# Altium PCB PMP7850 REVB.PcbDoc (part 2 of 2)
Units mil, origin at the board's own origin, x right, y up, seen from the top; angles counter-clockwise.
Board outline 4000 x 3000 mil, 4 copper layers (Top Layer, MidLayer1, MidLayer2, Bottom Layer), stack 61.2 mil thick; 106 components, 51 nets, 290 pads, 278 vias.
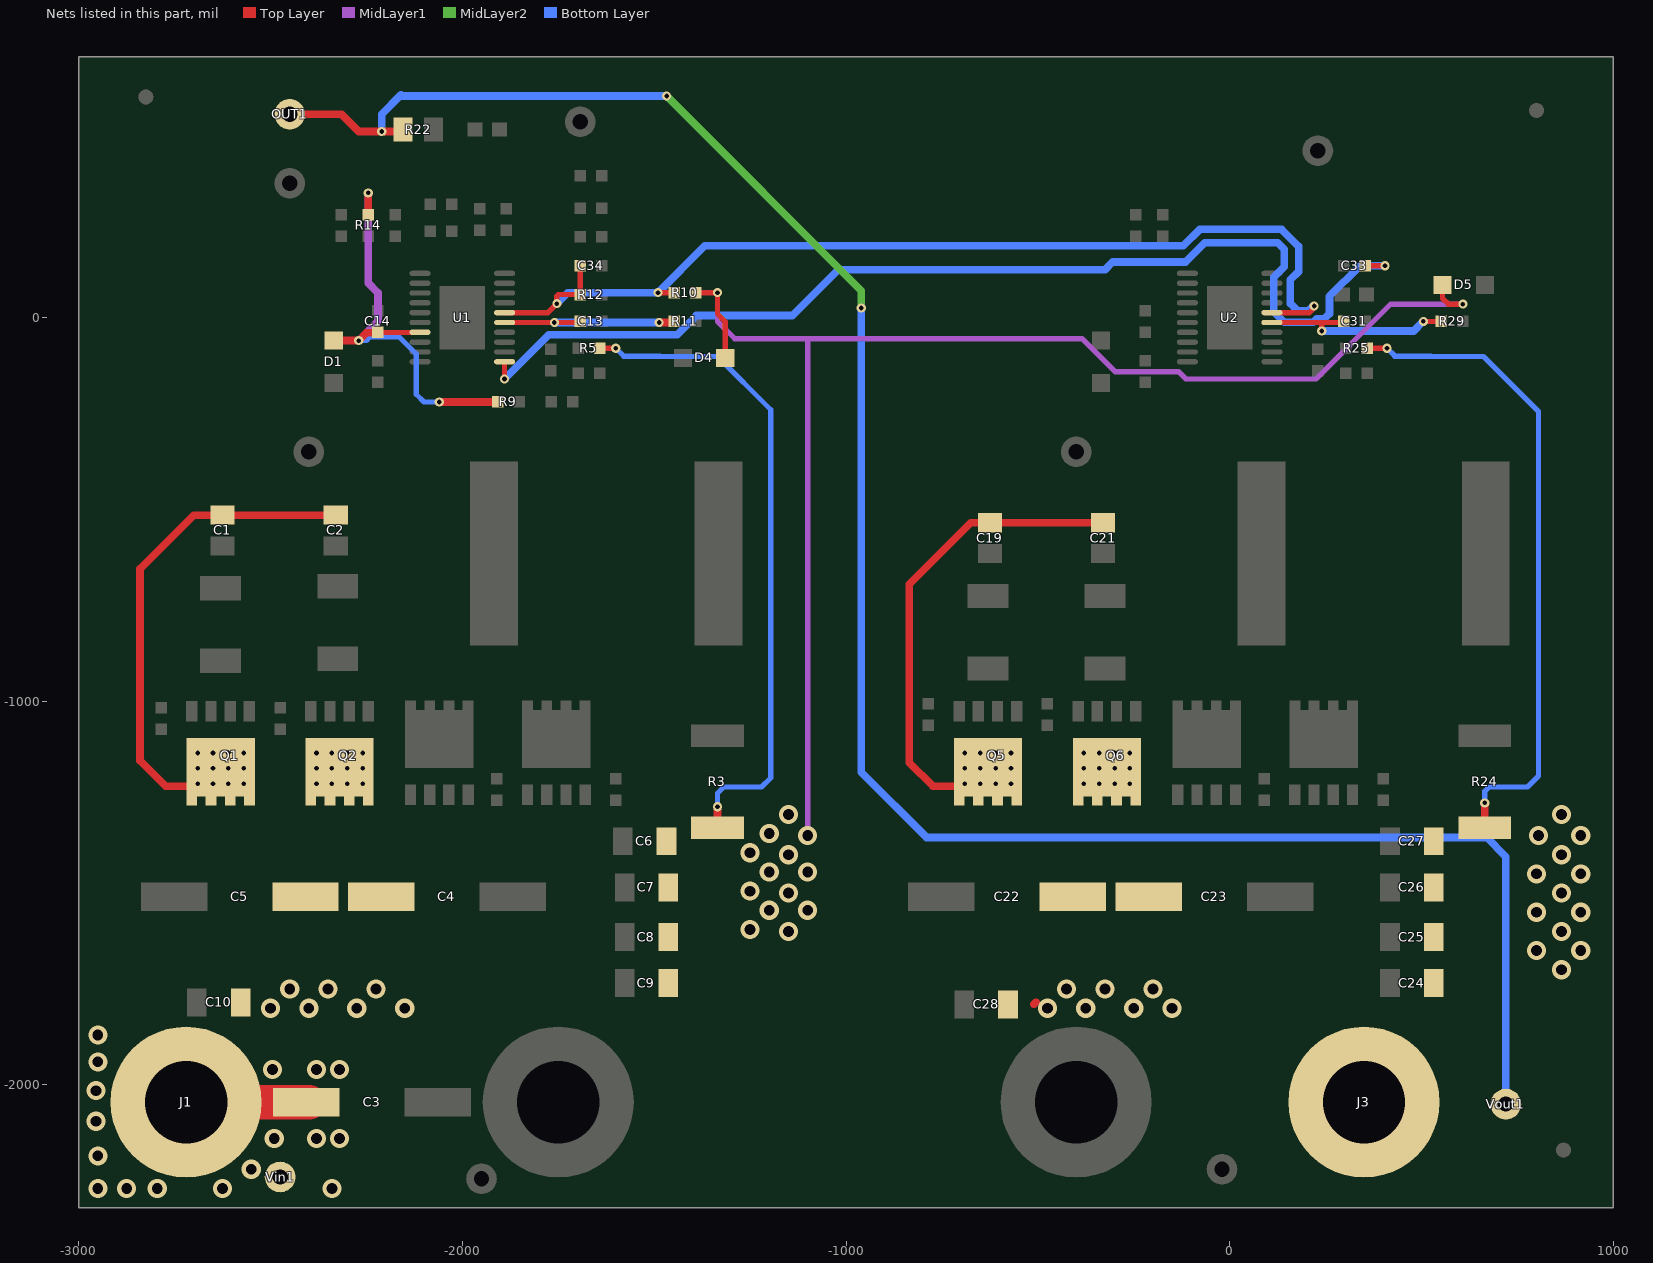
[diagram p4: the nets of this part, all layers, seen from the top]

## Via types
v1: diameter 24, hole 12, Top Layer to Bottom Layer, 169 vias
v2: diameter 50, hole 28, Top Layer to Bottom Layer, 101 vias
v3: diameter 30, hole 15, Top Layer to Bottom Layer, 8 vias

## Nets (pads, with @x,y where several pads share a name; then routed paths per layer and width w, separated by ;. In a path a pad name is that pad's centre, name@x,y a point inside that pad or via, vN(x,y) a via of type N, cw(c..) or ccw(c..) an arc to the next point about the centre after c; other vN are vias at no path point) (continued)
"SYNC OUT1": C33.1 U1.1 | length 2845.8
  Top Layer w13.78: v1(-1890,-160) -1890,-115.39 U1.1@-1889.76,-115.16 ; C33.1@353,135 v1(405,135)
  Bottom Layer w20: v1(-1890,-160) -1774.8,-44.8 -1440,-44.8 -1390,5.2 -1139.8,5.2 -1020,125 -325,125 -305,145 -115,145 -65,195 125,195 142.24,177.76 142.24,132.24 115,105 115,15 142,-12 217.75,-12 226.75,-3 247,-3 260,10 260,55 340,135 v1(405,135)
UVLO: C34.1 R10.1 R12.2 U1.6 U2.6 | length 2720.9
  Top Layer w13.78: U1.6@-1889.76,12.8 -1777.2,12.8 v1(-1753.6,36.4) -1753.6,56.4 -1750,60 R12.2@-1701.5,60 ; R12.2@-1693,60 C34.1@-1693,135 ; v1(-1490,65) R10.1@-1448,65 ; U2.6@110.24,12.8 207.8,12.8 220,25 v1(220,30)
  Bottom Layer w20: v1(-1753.6,36.4) -1725,65 v1(-1490,65) -1368.24,186.76 -120.55,186.76 -77.32,230 135,230 180,185 180,120 158,98 158,36.75 176.75,18 205.32,18 217.32,30 v1(220,30)
VCC: C14.1 D1.2 R9.2 R14.2 U1.17 | length 1205
  Top Layer w13.78: C14.1@-2219.61,-38.39 -2219.11,-38.89 -2110.74,-38.89 U1.17@-2110.24,-38.39
  Top Layer w20: D1.2@-2335,-59.88 -2270.12,-59.88 -2250,-39.76 -2221.76,-39.76 C14.1@-2220,-38 ; R14.2@-2245,268 v1(-2245,325) ; v1(-2060,-220) R9.2@-1908,-220
  MidLayer1 w20: v1(-2270,-60) -2220,-10 -2220,65 -2245,90 v1(-2245,325)
  Bottom Layer w13.78: v1(-2270,-60) -2250,-60 -2240,-50 -2165,-50 -2120,-95 -2120,-200 -2100,-220 v1(-2060,-220)
VIN1: C13.1 R11.1 U1.5 | length 501.1
  Top Layer w13.78: U1.5@-1889.76,-12.8 v1(-1760,-12.8) -1705.8,-12.8 C13.1@-1703,-10
  Top Layer w20: v1(-1487.2,-12.8) -1450.8,-12.8 R11.1@-1448,-10
  Bottom Layer w20: v1(-1760,-12.8) v1(-1487.2,-12.8)
VIN2: C31.1 R29.1 U2.5 | length 532.5
  Top Layer w13.78: U2.5@110.24,-12.8 240,-12.8 ; v1(240,-35) 240,-12.8 ; C31.1@297,-10 294.2,-12.8 240,-12.8 ; v1(505,-10) R29.1@552,-10
  Bottom Layer w20: v1(240,-35) 480,-35 v1(505,-10)
"VIN 6-8.4V": C3.1 C6.1 C7.1 C8.1 C9.1 C24.1 C25.1 C26.1 C27.1 D4.2 D5.2 J1.1 R3.1 R5.2 R10.2 R24.1 R25.2 Vin1.1 | length 7543.2
  Top Layer w13.78: R5.2@-1642,-80 v1(-1600,-80) ; R10.2@-1392,65 v1(-1335,65) -1335,10 -1314.88,-10.12 D4.2@-1314.88,-105 ; R25.2@358,-80 v1(410,-80) ; D5.2@554.88,85 554.88,50.12 570,35 v1(608,35)
  Top Layer w20: R3.1@-1335,-1330.08 v1(-1335,-1275) ; R24.1@665,-1330.08 v1(665,-1265)
  Top Layer w90: J1.1@-2720,-2045 C3.1@-2398.7,-2045
  MidLayer1 w13.78: v1(-1335,65) -1335,-10 -1290,-55 -1105,-55 ; v2(-1100,-1350) -1100,-60 -1105,-55 ; v1(608,35) 420,35 225,-160 -114.14,-160 -133.25,-140.89 -299.11,-140.89 -385,-55 -1105,-55
  Bottom Layer w13.78: v1(-1600,-80) -1579.39,-100.61 -1485.15,-100.61 -1484.54,-101.22 -1335.15,-101.22 -1196.22,-240.15 -1196.22,-1199.85 -1220.15,-1223.78 -1318.78,-1223.78 -1335,-1240 v1(-1335,-1275) ; v1(410,-80) 430.61,-100.61 524.85,-100.61 525.46,-101.22 661.22,-101.22 805,-245 805,-1195 776.22,-1223.78 676.22,-1223.78 665,-1235 v1(665,-1265)
  other v2: -2950,-2270 -2875,-2270 -2795,-2270 -2625,-2270 -2340,-2270 -2550,-2220 -2950,-2185 -2490,-2140 -2380,-2140 -2320,-2140 -2955,-2095 -2955,-2015 -2495,-1960 -2380,-1960 -2320,-1960 -2950,-1940 -2950,-1870 865,-1700 800,-1650 915,-1650 -1150,-1600 865,-1600 -1250,-1595 800,-1550 915,-1550 -1200,-1545 -1100,-1545 -1150,-1500 865,-1500 -1250,-1495 800,-1450 915,-1450 -1200,-1445 -1100,-1445 -1150,-1400 865,-1400 -1250,-1395 805,-1350 915,-1350 -1200,-1345 -1150,-1295 865,-1295
"VOUT +12V": C1.1 C2.1 C4.1 C5.1 C10.1 C19.1 C21.1 C22.1 C23.1 C28.1 J3.1 OUT1.1 Q1.5 Q1.6 Q1.7 Q1.8 Q1.9 Q2.5 Q2.6 Q2.7 Q2.8 Q2.9 Q5.5 Q5.6 Q5.7 Q5.8 Q5.9 Q6.5 Q6.6 Q6.7 Q6.8 Q6.9 R22.1 Vout1.1 | length 8145.6
  Top Layer w20: Q1.9@-2600,-1221.98 -2773.02,-1221.98 -2840,-1155 -2840,-655 -2700,-515 C2.1@-2330,-515 ; OUT1.1@-2450,530 -2315,530 -2270,485 v1(-2210,485) R22.1@-2160,485 ; Q5.9@-600,-1221.98 -773.02,-1221.98 -835,-1160 -835,-695 -675,-535 C21.1@-330,-535 ; -510,-1790 -505,-1785
  MidLayer2 w20: v1(-1467.5,577.5) -960.12,70.12 v1(-960.12,25)
  Bottom Layer w20: v1(-2210,485) -2210,530 -2160,580 ; -2160,577.5 v1(-1467.5,577.5) ; v1(-960.12,25) -960.12,-1185.12 -790.24,-1355 670,-1355 720,-1405 Vout1.1@720,-2050
  other v1: -2690,-1215 -2650,-1215 -2610,-1215 -2570,-1215 -2380,-1215 -2340,-1215 -2300,-1215 -2260,-1215 -690,-1215 -650,-1215 -610,-1215 -570,-1215 -380,-1215 -340,-1215 -300,-1215 -260,-1215 -2690,-1175 -2650,-1175 -2610,-1175 -2570,-1175 -2380,-1175 -2340,-1175 -2300,-1175 -2260,-1175 -690,-1175 -650,-1175 -610,-1175 -570,-1175 -380,-1175 -340,-1175 -300,-1175 -260,-1175 -2690,-1135 -2650,-1135 -2610,-1135 -2570,-1135 -2380,-1135 -2340,-1135 -2300,-1135 -2260,-1135 -690,-1135 -650,-1135 -610,-1135 -570,-1135 -380,-1135 -340,-1135 -300,-1135 -260,-1135
  other v2: -2500,-1800 -2400,-1800 -2275,-1800 -2150,-1800 -475,-1800 -375,-1800 -250,-1800 -150,-1800 -2450,-1750 -2350,-1750 -2225,-1750 -425,-1750 -325,-1750 -200,-1750
pads on no net: FID1.1 FID2.1 FID3.1 FID4.1 FID5.1 FID6.1 Q1.0 Q2.0 Q3.0 Q4.0 Q5.0 Q6.0 Q7.0 Q8.0 U2.1

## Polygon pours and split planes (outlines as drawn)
GND on Top Layer "Top Layer-GND" (solid, remove dead copper, pour order 42): -1230,705 -1230,465 -2430,465 -2430,-355 -2560,-485 -2635,-485 -2810,-660 -2810,-1255 -3000,-1255 -3005,-1260 -3005,685
GND on Top Layer "Top Layer-GND" (solid, remove dead copper, pour order 44): -2365,250 -2365,360 -2285,440 -1480,440 -1480,-250 -1730,-250 -1730,-200 -1560,-200 -1560,-35 -1665,-35 -1665,330 -1715,330 -1715,245 -1745,215 -1745,185 -1845,85 -1855,85 -1855,265 -1910,265 -1910,330 -2145,330 -2145,250 -2200,250 -2200,355 -2285,355 -2295,345 -2295,250
GND on Top Layer "Top Layer-GND" (solid, remove dead copper, pour order 35): -2160,-1220.1 -2160,-1330.2 -2100,-1390.2 -2100,-2320.2 -1535,-2320.2 -1535,-1300 -1715,-1300 -1715,-1220.08 -1845,-1219.87 -1845,-1300 -2020,-1300 -2020,-1219.96
CSN1_N on Top Layer "Top Layer-CSN1_N" (solid, remove dead copper, pour order 30): -1415,-375 -1415,-1120 -1245,-1120 -1245,-375
SW1_P on Top Layer "Top Layer-SW1" (solid, remove dead copper, pour order 26): -1665,-355 -1665,-1175 -2210,-1175 -2210,-1055 -2670,-1055 -2670,-985 -2700,-985 -2700,-770 -2255,-770 -2255,-355
"VIN 6-8.4V" on Top Layer "Top Layer-VIN 6-8.4V" (solid, remove dead copper, pour order 40): 485,-1250 995,-1250 995,-1790 485,-1790
"VIN 6-8.4V" on Top Layer "Top Layer-VIN 6-8.4V" (solid, remove dead copper, pour order 48): -3005,-1835 -3005,-2320 -3000,-2315 -2275,-2315 -2275,-1835
GND on Top Layer "Top Layer-GND" (solid, remove dead copper, pour order 41): 1000,-1801.75 1000,-2319.37 1005,-2325 -2250,-2325 -2250,-1801.75
GND on Top Layer "Top Layer-No Net" (solid, remove dead copper, pour order 46): -195,250 -195,340 470,340 470,-25 475,-30 335,-30 335,80 430,80 430,165 290,165 215,90 180,90 140,85 140,220 115,250
"VIN 6-8.4V" on Top Layer "Top Layer-VIN 6-8.4V" (solid, remove dead copper, pour order 34): -1015,-1790 -1015,-1250 -1510,-1250 -1510,-1790
GND on Top Layer "Top Layer-GND" (solid, remove dead copper, pour order 39): -1430,685 -380,685 -380,-495 -670,-495 -810,-635 -810,-1225 -1645,-1225 -1645,-300 -1430,-300
GND on Top Layer "Top Layer-GND" (solid, remove dead copper, pour order 43): -660,685 -660,370 525,370 525,-195 -165,-195 -165,-405 350,-405 350,-1225 1005,-1225 1005,685
CSN2_N on Top Layer "Top Layer-CSN2_N" (solid, remove dead copper, pour order 32): 580,-375 755,-375 755,-1115 750,-1120 580,-1120
GND on Top Layer "Top Layer-GND" (solid, remove dead copper, pour order 36): -1005,-1250 -745,-1250 -745,-1460 -570,-1460 -570,-1755 -571.45,-1756.45 -566.42,-2325 -1005,-2325
SW2_P on Top Layer "Top Layer-SW2" (solid, remove dead copper, pour order 27): 335,-400 -255,-400 -255,-795 -700,-795 -700,-985 -675,-985 -675,-1030 -675,-1050 -525,-1050 -525,-1030 -360,-1030 -360,-1050 -160,-1050 -160,-1175 335,-1175
GND on Top Layer "Top Layer-GND" (solid, remove dead copper, pour order 37): -165,-1215 -165,-1330.31 -105,-1390.59 -105,-2320 475,-2320 475,-1290 285,-1290 285,-1215 155,-1215 155,-1295 -20,-1295 -20,-1215
"VOUT +12V" on Top Layer "Top Layer-VOUT +12V" (solid, remove dead copper, pour order 29): -720,-1095 -220,-1095 -220,-1335 -180,-1335 -115,-1400 -115,-1830 -560,-1830 -560,-1450 -720,-1450
GND on Top Layer "Top Layer-GND" (solid, remove dead copper, pour order 38): -3005,-1300 -2745,-1300 -2745,-1380 -2615,-1510 -2615,-1815 -3005,-1815
"VOUT +12V" on Top Layer "Top Layer-VOUT" (solid, remove dead copper, pour order 28): -2720,-1095 -2220,-1095 -2220,-1335 -2190,-1335 -2115,-1410 -2115,-1895 -2605,-1895 -2605,-1485 -2620,-1485 -2720,-1385
"VIN 6-8.4V" on MidLayer1 "MidLayer1-VIN 6-8.4V" (solid, remove dead copper, pour order 31): -3005,-2325 1005,-2325 1005,-470 -3005,-470
GND on MidLayer1 "MidLayer1-GND" (solid, remove dead copper, pour order 45): -3000,685 1005,685 1005,-420 -3000,-420
"VOUT +12V" on Bottom Layer "Bottom Layer-VOUT +12V" (solid, remove dead copper, pour order 33): -3010,-2320 1005,-2320 1010,-2325 1010,-1375 -3004.81,-1375
GND on Bottom Layer "Bottom Layer-GND" (solid, remove dead copper, pour order 25): -3005,685 1000,685 1000,-1400 -3005,-1400
GND on MidLayer2 "MidLayer2-GND" (solid, remove dead copper, pour order 47): -3000,-2345 1000,-2345 1000,680 -3000,680

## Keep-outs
Keep-Out Layer:
  lines w10: -3005,685 -3005,-2325 1005,-2325 1005,685 -3000,685
  text ".Layer_Name" at -2423,-3178.49 h60
  text "880" at 117.5,-3178.49 h60

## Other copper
Top Layer:
  rectangle net GND: -2060,-150 -1940,170
  rectangle net GND: -60,-155 60,155
  pour cut-out: -1365,-1300 -1365,-1255 -1300,-1255 -1300,-1300
  pour cut-out: 635,-1245 700,-1245 700,-1290 635,-1290
  text ".Layer_Name" at -2423,-3178.49 h60
  text "880" at 117.5,-3178.49 h60
MidLayer1:
  pour cut-out: 635,-1240 635,-1290 700,-1290 700,-1240
  pour cut-out: -1365,-1250 -1300,-1250 -1300,-1300 -1365,-1300
Bottom Layer:
  pour cut-out: 735,-2015 735,-1435 705,-1435 705,-2015
  pour cut-out: 620,-1120 755,-1120 755,-285 625,-155 450,-155 450,-185 375,-185 375,-45 660,-45 830,-215 830,-1265 790,-1305 620,-1305
  pour cut-out: -1635,-50 -1635,-170 -1545,-170 -1545,-150 -1360,-150 -1245,-265 -1245,-1110 -1370,-1110 -1370,-1310 -1305,-1310 -1270,-1275 -1180,-1275 -1170,-1265 -1170,-225 -1320,-75 -1545,-75 -1545,-50
  text ".Layer_Name" at -2423,-3178.49 h60
  text "880" at 117.5,-3178.49 h60

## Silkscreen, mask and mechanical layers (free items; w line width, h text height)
Top Overlay:
  text ".Pcb_File_Name_No_Path" at -1400,455 h60
  text "©" at -1075,330 h105
  text ".CopyrightYear" at -975,330 h60
  text "TI" at -699,330 h60
  text "SW" at -565,-305 h40
  text "SW" at -2570,-310 h40
  text "VIN" at -2570,-1905 h40
  text "GND" at -1485,-1945 h60
  text "VOUT" at 595,-1950 h60
  text "GND" at -150,-1955 h60
  text ".Layer_Name" at -2423,-3178.49 h60
  text "880" at 117.5,-3178.49 h60
Bottom Overlay:
  text "MADE IN U.S." at -425,520 h60
  text "UL94V-0" at 90,515 h60
  text ".PCB_SilkRev" at -864,355 h60
  text ".PCB_CopperRev" at -684,355 h60
  text "-" at -625,355 h60
  text ".PRJ_BasePN" at -264,355 h60
  text "551" at -99,355 h60
  text ".Layer_Name" at -2423,-3178.49 h60
  text "880" at 117.5,-3178.49 h60
Top Paste:
  text ".Layer_Name" at -2423,-3178.49 h60
  text "881" at 117.5,-3178.49 h60
Bottom Paste:
  text ".Layer_Name" at -2423,-3178.49 h60
  text "881" at 117.5,-3178.49 h60
Top Solder:
  text ".Layer_Name" at -2423,-3178.49 h60
  text ".Layer_Name" at -2423,-3178.49 h60
  text "880" at 117.5,-3178.49 h60
Bottom Solder:
  text ".Layer_Name" at -2423,-3178.49 h60
  text "880" at 117.5,-3178.49 h60
Drill Guide:
  text ".Layer_Name" at -2423,-3178.49 h60
  text "880" at 117.5,-3178.49 h60
M1 Board Outline:
  the board outline again, w10
  text ".Layer_Name" at -2423,-3178.49 h60
  text "880" at 117.5,-3178.49 h60
M2 Board Dimensions:
  rectangle: -2875.5,-2730.5 -2500.5,-2605.5
  rectangle: -3000.5,-2605.5 -2875.5,-2480.5
  lines w7: -3000.5,-2605.5 -2000.5,-2605.5 ; -2875.5,-2730.5 -2875.5,-2480.5 ; -2750.5,-2730.5 -2750.5,-2480.5 ; -2500.5,-2730.5 -2500.5,-2480.5 ; -2250.5,-2730.5 -2250.5,-2480.5 ; -3000.5,-2730.5 -3000.5,-2480.5 -2000.5,-2480.5 -2000.5,-2730.5 -3000.5,-2730.5
  lines w10: -3000.5,-2795.5 -3000.5,-2775.5 ; -2940.5,-2805.5 -3000.5,-2785.5 ; -2940.5,-2765.5 -3000.5,-2785.5 ; -2776.42,-2785.5 -3000.5,-2785.5 ; -2224.58,-2785.5 -2000.5,-2785.5 ; -2060.5,-2805.5 -2000.5,-2785.5 ; -2060.5,-2765.5 -2000.5,-2785.5 ; -2000.5,-2795.5 -2000.5,-2775.5
  text "1000 (mil)" at -2766.42,-2821.49 h60
  text ".Layer_Name" at -2423,-3178.49 h60
  text "880" at 117.5,-3178.49 h60
M3 3D STEP Top:
  text ".Layer_Name" at -2423,-3178.49 h60
  text "880" at 117.5,-3178.49 h60
M4 3D STEP Bottom:
  text ".Layer_Name" at -2423,-3178.49 h60
  text "880" at 117.5,-3178.49 h60
M5 Assembly Top:
  lines w7: -3292,-3250.17 3308,-3250.17 ; -3292,-3046.83 3310,-3046.83 ; -3292,-2843.5 -3292,-3453.5 713,-3453.5 3310,-3453.5 3310,-2843.5 -3291.5,-2843.5 -3291.5,-3453.5 -1716,-3453.5 ; -827,-3249 -827,-2843.5 ; 926,-3453 926,-3253 ; 1902,-3250 1902,-3047.17
  text "COMPONENTS MARKED 'DNP' SHOULD NOT BE POPULATED, AND MAY NOT BE IN BILL OF MATERIALS" at -1846.5,-2638.5 h60
  text "ASSEMBLY VARIANT:" at -1847,-2754 h60
  text ".VariantName" at -811,-2754 h60
  text "PCB VIEWED FROM TOP SIDE" at -3228.5,-2975.67 h60
  text "PROJECT NAME =" at -752,-2975.67 h60
  text ".PRJ_Title" at 117.5,-2975.67 h60
  text "-" at 662,-3176.49 h60
  text ".PCB_SilkRev" at 919,-3176.49 h60
  text "TEXAS INSTRUMENTS" at 1973,-3176.49 h60
  text "LAYER NAME =" at -3228.5,-3178.49 h60
  text "ARTWORK #    =" at -752,-3178.49 h60
  text ".prj_BasePN" at 293.5,-3178.49 h60
  text ".PCB_CopperRev" at 729.5,-3178.49 h60
  text "PLOT NAME =" at -3228.5,-3384.34 h60
  text ".plot_File_Name" at -2423,-3384.34 h60
  text "GENERATED    :" at 998,-3384.34 h60
  text ".Print_Date" at 1867.5,-3384.34 h60
  text ".Print_Time" at 2596.5,-3384.34 h60
M6 Assembly Bottom:
  lines w7: -3292,-3046.83 3310,-3046.83 ; -3290,-3250.17 3310,-3250.17 ; -1884,-3250.5 -1884,-3047.17 ; -866,-3453 -866,-3251 ; 845,-3249 845,-2843.5 ; 1734,-3453.5 3309.5,-3453.5 3309.5,-2843.5 -3292,-2843.5 -3292,-3453.5 -695,-3453.5 3310,-3453.5 3310,-2843.5
  text "COMPONENTS MARKED 'DNP' SHOULD NOT BE POPULATED, AND MAY NOT BE IN BILL OF MATERIALS" at 3102,-2638 h60
  text ".VariantName" at 2058,-2754 h60
  text "ASSEMBLY VARIANT:" at 3097,-2754 h60
  text ".PRJ_Title" at -99.5,-2975.67 h60
  text "PROJECT NAME =" at 770,-2975.67 h60
  text "PCB VIEWED FROM BOTTOM SIDE" at 3246.5,-2975.67 h60
  text "-" at -685,-3176.49 h60
  text "TEXAS INSTRUMENTS" at -1955,-3178.49 h60
  text ".PCB_SilkRev" at -916,-3178.49 h60
  text ".PCB_CopperRev" at -715,-3178.49 h60
  text ".prj_BasePN" at -275.5,-3178.49 h60
  text "880" at -92,-3178.49 h60
  text "ARTWORK #    =" at 770,-3178.49 h60
  text "LAYER NAME =" at 3246.5,-3178.49 h60
  text ".Print_Time" at -2578.5,-3384.34 h60
  text ".Print_Date" at -1849.5,-3384.34 h60
  text "GENERATED    :" at -980,-3384.34 h60
  text ".plot_File_Name" at 2441,-3384.34 h60
  text "PLOT NAME =" at 3246.5,-3384.34 h60
M9 Title Sheet:
  drawing of 57 lines, arcs and shapes, not listed
  text "1" at -2260.16,5716.5 h70
  text "2" at 235.5,5716.5 h70
  text "3" at 2724.84,5716.5 h70
  text "4" at 5231.51,5716.5 h70
  text "5" at 7730.5,5716.5 h70
  text "6" at 10235.5,5716.5 h70
  text "A" at -3416.5,4573.5 h70
  text "A" at 11383.5,4573.5 h70
  text "B" at -3416.5,2193.5 h70
  text "B" at 11383.5,2193.5 h70
  text "C" at -3416.5,-181.5 h70
  text "C" at 11383.5,-181.5 h70
  text "PROJECT TITLE:" at 8343.5,-2042.5 h45
  text ".PRJ_Title" at 8393.5,-2175.83 h70
  text "FILE NAME:" at 8343.5,-2343.5 h45
  text ".PCB_File_Name_No_Path" at 8393.5,-2463.5 h70
  text "D" at -3416.5,-2551.5 h70
  text "D" at 11383.5,-2551.5 h70
  text "FAB DRAWING NUMBER:" at 8343.5,-2633.5 h45
  text "551" at 8393.5,-2788.49 h70
  text ".PRJ_BasePN" at 8588.5,-2788.49 h70
  text "-" at 8997,-2788.49 h70
  text ".PCB_CopperRev" at 9070,-2788.49 h70
  text ".PCB_SilkRev" at 9295,-2788.49 h70
  text "Texas Instruments (TI) and/or its licensors do not warrant the accuracy or completeness of this specification" at 3374,-2925.34 h45
  text "DESIGNED FOR:" at 8343.5,-2943.5 h45
  text "or any information contained therein. TI and/or its licensors do not warrant that this design will meet" at 3329.01,-3038 h45
  text ".PRJ_Customer" at 8393.5,-3083.5 h70
  text "the specifications, will be suitable for your application or fit for any particular purpose, or will operate in" at 3329.01,-3150.67 h45
  text ".Layer_Name" at -2423,-3178.49 h60
  text "880" at 117.5,-3178.49 h60
  text "ALTIUM DESIGNER VERSION:" at 9888.5,-3243.5 h45
  text "an implementation. TI and/or its licensors do not warrant that the design is production worthy. You should" at 3329.01,-3263.33 h45
  text ".print_Scale" at 8393.5,-3345.5 h70
  text "completely validate and test your design implementation to confirm the system functionality for your application." at 3374,-3376 h45
  text ".Application_BuildNumber" at 9938.5,-3376.83 h70
  text "1" at -2260.16,-3583.5 h70
  text "2" at 235.5,-3583.5 h70
  text "3" at 2724.84,-3583.5 h70
  text "4" at 5231.51,-3583.5 h70
  text "5" at 7730.5,-3583.5 h70
  text "6" at 10235.5,-3583.5 h70
M10 Fab Notes:
  drawing of 203 lines, arcs and shapes, not listed
  text "DESIGN INFORMATION" at 9381.02,4490 h60
  text "(REFER ALSO ARRAY/PANEL PROFILING INFORMATION)" at 9019.46,4328.29 h60
  text "BOARD SIZE" at 8333.46,4324 h60
  text "4000MIL" at 8795.78,4196.18 h60
  text "X" at 9301.46,4196.18 h60
  text "3000MIL" at 9532.78,4196.18 h60
  text "Number of Layers :" at 8736.46,3999 h60
  text "4" at 9831.27,3989 h60
  text "MIN. TRACK WIDTH:" at 8736.46,3860 h60
  text "13" at 9832.7,3860 h60
  text "MIL" at 9987.46,3860 h60
  text "MIN. CLEARANCE:" at 8736.46,3728 h60
  text "8" at 9832.7,3728 h60
  text "MIL" at 9987.46,3728 h60
  text "MIN. VIA PAD SIZE:" at 8736.46,3596 h60
  text "20" at 9802.71,3596 h60
  text "MIL" at 9987.46,3596 h60
  text "0.127mm (5MIL)" at 9431.46,3454.29 h60
  text "MINIMUM ANNULAR RING" at 8407.23,3450 h60
  text "EXTERNAL" at 10139.46,3450 h60
  text "PER" at 8607.23,3332 h60
  text "IPC-D-275 CLASS 2 LEVEL C" at 8827.23,3332 h60
  text "MIL, HOLES" at 10315.46,3219.71 h60
  text "+/-" at 9923,3219 h60
  text "+/-" at 10777,3219 h60
  text "REGISTRATION TOLERANCES:" at 8407.23,3214 h60
  text "METAL" at 9607,3214 h60
  text "5" at 10183.2,3214 h60
  text "3" at 11016.2,3214 h60
  text "MIL" at 11132.46,3214 h60
  text "MATERIAL:" at 8332.46,3004.54 h60
  text "FR-4 High Tg" at 9318.9,2864.21 h60
  text "FR-4" at 8793.46,2855.64 h60
  text "OTHER" at 10241.46,2855.64 h60
  text "X" at 8605,2855 h60
  text "62 MIL (1.6mm) +/-10%" at 9073.56,2692.92 h60
  text "THICKNESS:" at 8407.23,2688.64 h60
  text "X" at 8945.4,2688.64 h60
  text "OTHER" at 10358.46,2688.64 h60
  text "TOLERANCE:" at 8407.23,2530.64 h60
  text "X" at 9246.53,2530.64 h60
  text "ANSI IPC-6012 TYPE 3 CLASS 2" at 9433.48,2530.64 h60
  text "OTHER +/-" at 9433.46,2374.64 h60
  text "BOW & TWIST:" at 8407.23,2217.64 h60
  text "X" at 9246.53,2217.64 h60
  text "ANSI IPC-6012 TYPE 3 CLASS 2" at 9433.48,2217.64 h60
  text "OTHER +/-" at 9433.46,2059.13 h60
  text "COPPER THICKNESS (FINISHED):" at 8332.46,1923.64 h60
  text "1.4MIL (1oz)" at 9212.46,1770.92 h60
  text "2MIL (1.4oz)" at 9979.46,1770.92 h60
  text "2.8MIL (2oz)" at 10706.46,1770.92 h60
  text "OUTER:" at 8689.46,1766.64 h60
  text "X" at 9084,1766 h60
  text "0.7MIL (0.5oz)" at 9562.46,1613.92 h60
  text "2.8MIL (2oz)" at 10406.46,1613.92 h60
  text "INNER SIGNAL:" at 8689.46,1609.64 h60
  text "X" at 9435.42,1609.64 h60
  text "DRILLING:" at 8332.46,1470.64 h60
  text "REFERENCE:" at 8407.23,1353.64 h60
  text "X" at 9055.46,1353.64 h60
  text "AS SHOWN" at 9242.46,1353.64 h60
  text "X" at 9956.46,1353.64 h60
  text "NC_DRILL FILES" at 10093.46,1353.64 h60
  text "PTH MIN COPPER THICKNESS:" at 8407.23,1195.64 h60
  text "X" at 9757.46,1195.64 h60
  text "1MIL" at 9894.46,1195.64 h60
  text "OTHER" at 10391.46,1195.64 h60
  text "BOARD FINISH:" at 8332.46,1036.64 h60
  text "SILKSCREEN:" at 8487.68,918.64 h60
  text "X" at 9436.46,918.64 h60
  text "TOP" at 9562.46,918.64 h60
  text "X" at 9946.46,918.64 h60
  text "BOTTOM" at 10073.46,918.64 h60
  text "SILKSCREEN COLOR:" at 8487.68,751.64 h60
  text "X" at 9435.42,751.64 h60
  text "WHITE" at 9562.46,751.64 h60
  text "OTHER" at 10073.46,751.64 h60
  text "SOLDER RESIST COLOR:" at 8487.68,581.64 h60
  text "X" at 9055.42,422.44 h60
  text "GREEN" at 9182.46,422.44 h60
  text "BLUE" at 9773.46,422.44 h60
  text "OTHER" at 10311.46,422.44 h60
  text "IMMERSION GOLD (ENIG)" at 9393.46,233.92 h60
  text "SURFACE FINISH:" at 8332.46,229.64 h60
  text "Pb-FREE HASL" at 10625.75,229.64 h60
  text "X" at 10485,225 h60
  text "OTHER" at 9393.46,72.64 h60
  text "X" at 9200,-100 h60
  text "ARRAY/PANEL:" at 8332.46,-106.36 h60
  text "CUT AND TRIM PER MECH LAYER 1" at 9393.46,-110.65 h60
  text "N.C. ROUTE" at 9393.46,-262.36 h60
  text "V. SCORE" at 10259.46,-262.36 h60
  text "CERTIFICATION:" at 8332.46,-399.36 h60
  text "MATERIALS AND WORKMANSHIP FOR ALL PCBS" at 9057.46,-399.36 h60
  text "TO MEET OR EXCEED THE REQUIREMENTS OF:" at 9057.46,-497.36 h60
  text "X" at 8683.96,-633.87 h60
  text "ANSI IPC-A-600F CLASS ->" at 8822.96,-633.87 h60
  text "X" at 10462.02,-633.87 h60
  text "2" at 10580.96,-633.86 h60
  text "1" at 10265.96,-635.36 h60
  text "3" at 10934.96,-635.36 h60
  text "X" at 8686.02,-793.36 h60
  text "UL 94V-0" at 8822.96,-793.36 h60
  text "X" at 9498.02,-793.36 h60
  text "RoHS" at 9634.96,-793.36 h60
  text "OTHER" at 10279.36,-793.36 h60
  text "PER ORDER" at 10676.42,-793.36 h60
  text "ADDITIONAL REQUIREMENTS:" at 8332.46,-934.36 h60
  text "MICROSECTION:" at 8407.23,-1049.36 h60
  text "YES" at 9312.96,-1049.36 h60
  text "X" at 10640,-1205 h60
  text "REQUIRED" at 10174.46,-1205.51 h60
  text "BARE BOARD ELEC. TEST:" at 8407.23,-1208.36 h60
  text "NONE" at 9712.96,-1208.36 h60
  text "PER ORDER" at 10766.46,-1208.36 h60
  text "MANUFACTURER'S ID/LOGO:" at 8407.23,-1365.36 h60
  text "RAIL" at 9872.96,-1369.65 h60
  text "METAL" at 10364.77,-1369.65 h60
  text "X" at 10750,-1370 h60
  text "SILK" at 10876.46,-1369.65 h60
  text ".Layer_Name" at -2423,-3178.49 h60
  text "880" at 117.5,-3178.49 h60
M11 Gerber Information:
  lines w7: -3292,-3250.17 3308,-3250.17 ; -3292,-3046.83 3310,-3046.83 ; -3292,-2843.5 -3292,-3453.5 713,-3453.5 3310,-3453.5 3310,-2843.5 -3291.5,-2843.5 -3291.5,-3453.5 -1716,-3453.5 ; -827,-3249 -827,-2843.5 ; 926,-3453 926,-3253 ; 1902,-3250 1902,-3047.17
  text "ALL ARTWORK VIEWED FROM TOP SIDE" at -3228.5,-2975.67 h60
  text "PROJECT NAME =" at -752,-2975.67 h60
  text ".PRJ_Title" at 117.5,-2975.67 h60
  text "-" at 662,-3176.49 h60
  text ".PCB_SilkRev" at 919,-3176.49 h60
  text "TEXAS INSTRUMENTS" at 1973,-3176.49 h60
  text "LAYER NAME =" at -3228.5,-3178.49 h60
  text "ARTWORK #    =" at -752,-3178.49 h60
  text ".prj_BasePN" at 293.5,-3178.49 h60
  text ".PCB_CopperRev" at 729.5,-3178.49 h60
  text "PLOT NAME =" at -3228.5,-3384.34 h60
  text ".plot_File_Name" at -2423,-3384.34 h60
  text "GENERATED    :" at 998,-3384.34 h60
  text ".Print_Date" at 1867.5,-3384.34 h60
  text ".Print_Time" at 2596.5,-3384.34 h60
M12 Stackup:
  drawing of 295 lines, arcs and shapes, not listed
  text "Layer" at 2276.2,4425 h60
  text "Name" at 2686.11,4425 h60
  text "Material" at 3615.85,4425 h60
  text "Thickness" at 4475.62,4425 h60
  text "Constant" at 5125.46,4425 h60
  text "Board Layer Stack" at 5695.32,4425 h60
  text "1" at 2276.2,4305 h60
  text "Top Overlay" at 2686.11,4305 h60
  text "2" at 2276.2,4185 h60
  text "Top Solder" at 2686.11,4185 h60
  text "Solder Resist" at 3615.85,4185 h60
  text "0.40mil" at 4475.62,4185 h60
  text "3.5" at 5125.46,4185 h60
  text "3" at 2276.2,4065 h60
  text "Top Layer" at 2686.11,4065 h60
  text "Copper" at 3615.85,4065 h60
  text "1.40mil" at 4475.62,4065 h60
  text "4" at 2276.2,3945 h60
  text "Dielectric1" at 2686.11,3945 h60
  text "FR-4" at 3615.85,3945 h60
  text "12.60mil" at 4475.62,3945 h60
  text "4.8" at 5125.46,3945 h60
  text "5" at 2276.2,3825 h60
  text "MidLayer1" at 2686.11,3825 h60
  text "Copper" at 3615.85,3825 h60
  text "0.70mil" at 4475.62,3825 h60
  text "6" at 2276.2,3705 h60
  text "Dielectric2" at 2686.11,3705 h60
  text "FR-4" at 3615.85,3705 h60
  text "31.80mil" at 4475.62,3705 h60
  text "4.8" at 5125.46,3705 h60
  text "7" at 2276.2,3585 h60
  text "MidLayer2" at 2686.11,3585 h60
  text "Copper" at 3615.85,3585 h60
  text "0.70mil" at 4475.62,3585 h60
  text "8" at 2276.2,3465 h60
  text "Dielectric3" at 2686.11,3465 h60
  text "FR-4" at 3615.85,3465 h60
  text "12.60mil" at 4475.62,3465 h60
  text "4.8" at 5125.46,3465 h60
  text "9" at 2276.2,3345 h60
  text "Bottom Layer" at 2686.11,3345 h60
  text "Copper" at 3615.85,3345 h60
  text "1.40mil" at 4475.62,3345 h60
  text "10" at 2276.2,3225 h60
  text "Bottom Solder" at 2686.11,3225 h60
  text "Solder Resist" at 3615.85,3225 h60
  text "0.40mil" at 4475.62,3225 h60
  text "3.5" at 5125.46,3225 h60
  text "11" at 2276.2,3105 h60
  text "Bottom Overlay" at 2686.11,3105 h60
  text ".Layer_Name" at -2423,-3178.49 h60
  text "880" at 117.5,-3178.49 h60
M13 Component Bodies Top:
  text ".Layer_Name" at -2423,-3178.49 h60
  text "880" at 117.5,-3178.49 h60
M14 Component Bodies Bottom:
  text ".Layer_Name" at -2423,-3178.49 h60
  text "880" at 117.5,-3178.49 h60
M15 Courtyards Top:
  text ".Layer_Name" at -2423,-3178.49 h60
  text "880" at 117.5,-3178.49 h60
M16 Courtyards Bottom:
  text ".Layer_Name" at -2423,-3178.49 h60
  text "880" at 117.5,-3178.49 h60
Drill Drawing:
  text ".legend" at 1185,-1160 h60
  text "Drill Table" at 1185,-1280 h60
  text ".Layer_Name" at -2423,-3178.49 h60
  text "880" at 117.5,-3178.49 h60

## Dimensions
-3000,-2320 to 1000,-2320 on M2 Board Dimensions
-3000,-2320 to -3000,680 on M2 Board Dimensions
